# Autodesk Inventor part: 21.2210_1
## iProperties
Created: 2012-07
Part Number: 21.2210_1
Material: Aluminum-6061
Description: L = 11.811", MILL TO 21.2210_1
Document SubType Name: Modeling
Designer: Administrator
Stock Number: 20.0994 PROFILE 30X60
Density: 2.71 g/cm^3
Vendor: F
Mass: 290.133 g
Surface Area: 1571.14 cm^2
Volume: 107.06 cm^3
Author: Administrator
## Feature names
1. Extrusion1
2. Extrusion2
3. Hole1
4. Extrusion3
5. Mirror1
